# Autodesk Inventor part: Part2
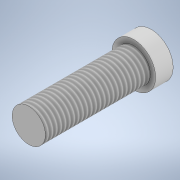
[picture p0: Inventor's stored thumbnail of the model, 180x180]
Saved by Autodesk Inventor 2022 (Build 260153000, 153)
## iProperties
Created: 2021-07
Part Number: Part2
Material: Generic
Document SubType Name: Modeling
Designer: Hp
Density: 1 g/cm^3
Appearance: Default
Author: Hp
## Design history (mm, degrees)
sketch "Sketch1"
  geometry: C1 r 12.5 at (0, 0); 1 further point
  constraints: 1 centre point, 1 coincident
  dimensions: "d0" = 25 diameter of C1
extrude "Extrusion1" new body sketch "Sketch1" distance "d1" = 10; taper "d2" = 0 deg
sketch "Sketch2"
  geometry: C1 r 9.5 at (0, 0); 1 further point
  constraints: 1 centre point, 1 coincident
  dimensions: "d3" = 19 diameter of C1
extrude "Extrusion2" join sketch "Sketch2" distance "d4" = 60; taper "d5" = 0 deg
thread "Thread1" dims "d6" = 60, "d7" = 0
body "Solid1"
